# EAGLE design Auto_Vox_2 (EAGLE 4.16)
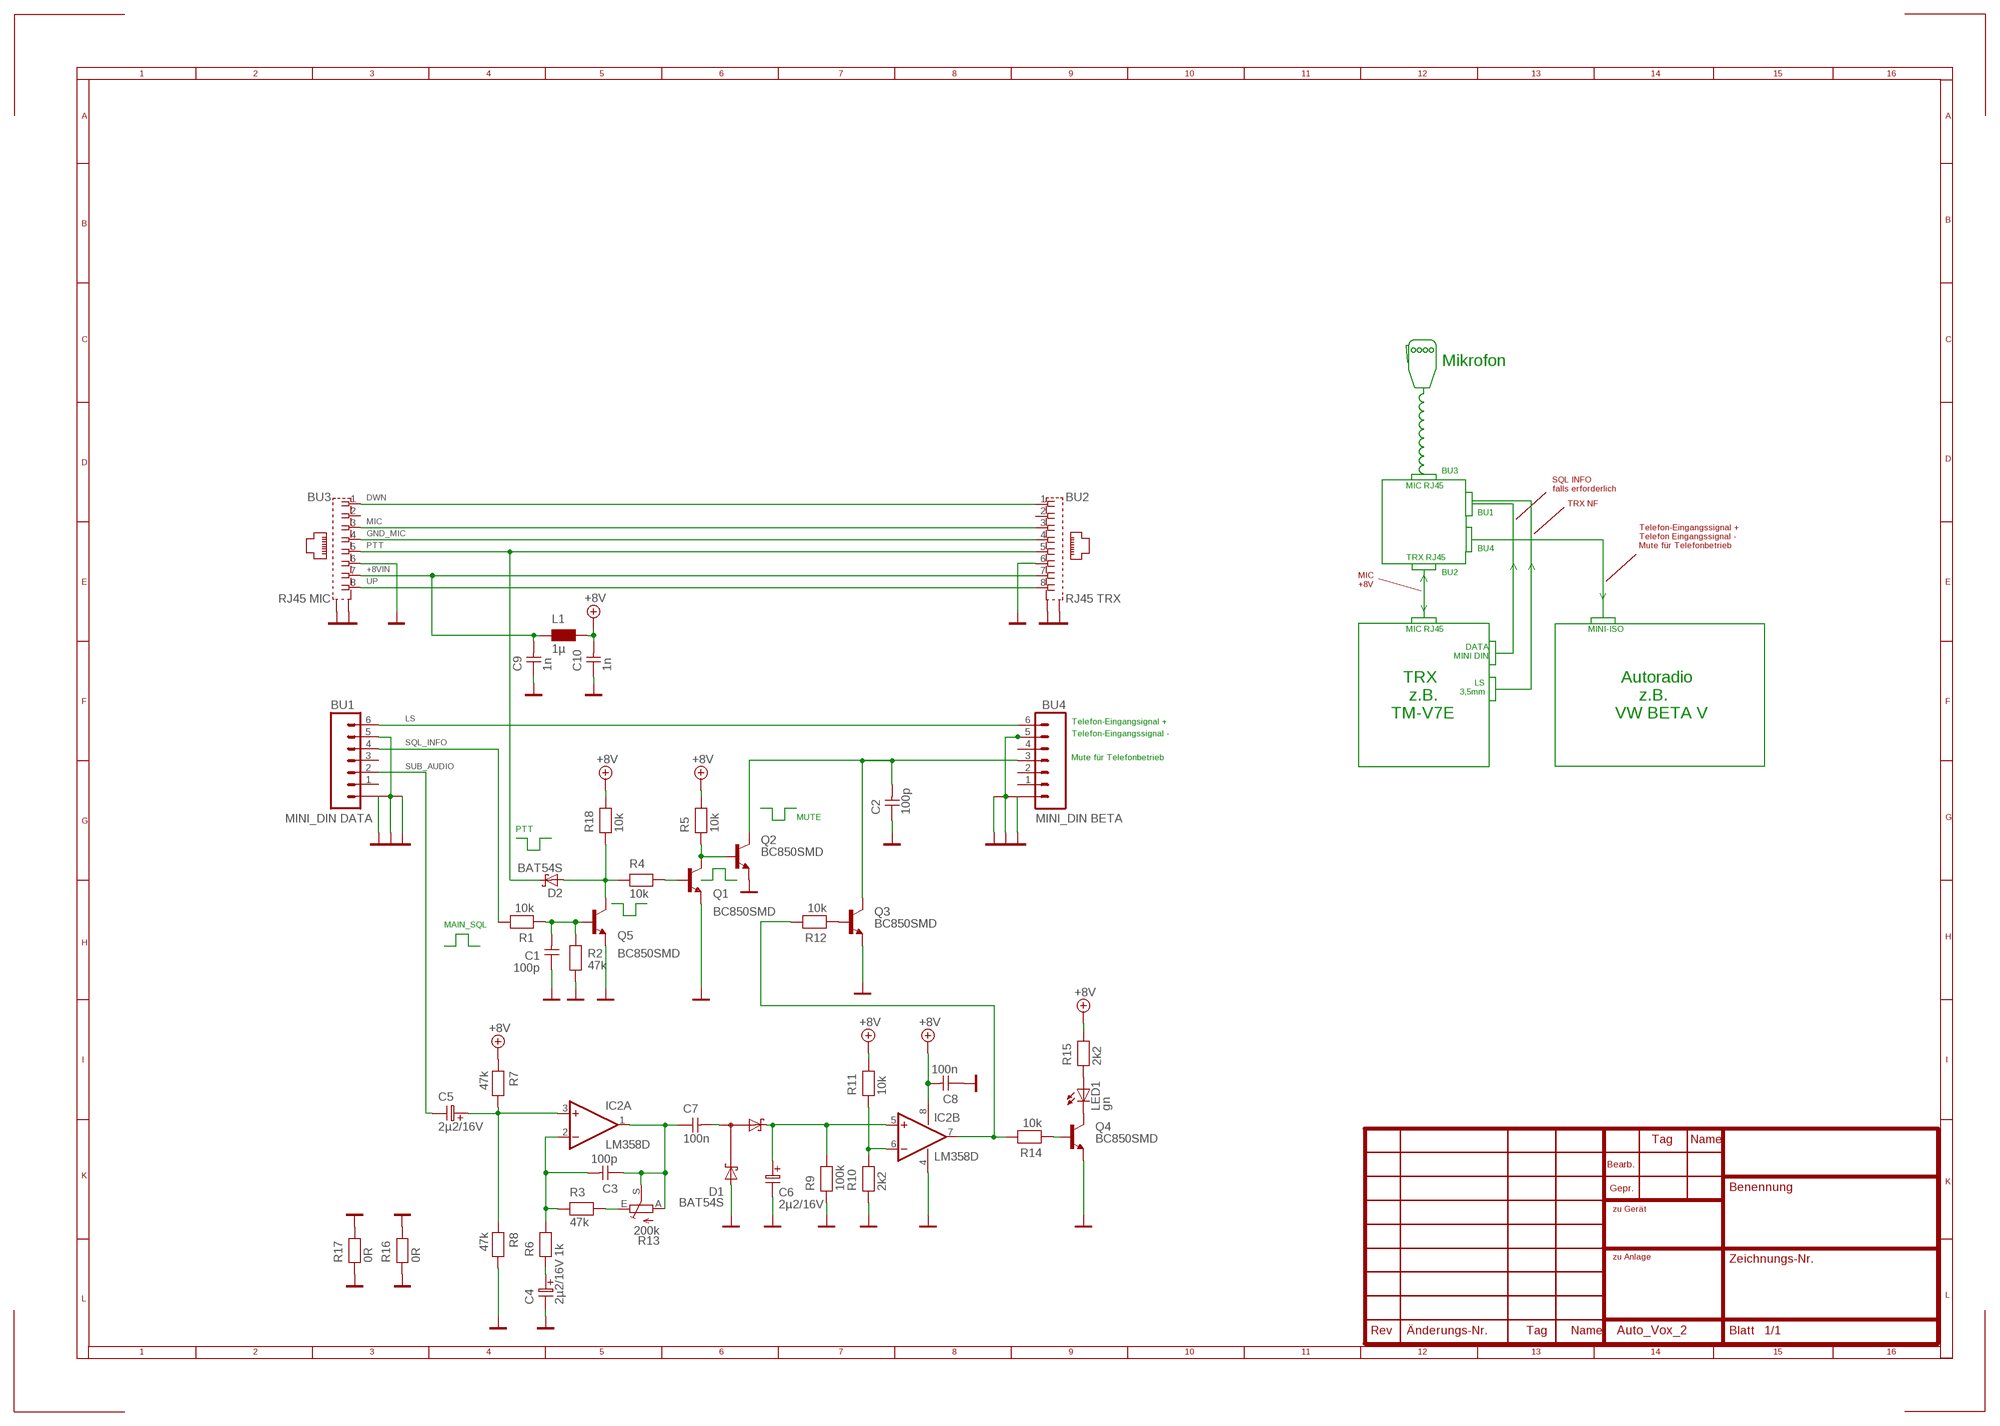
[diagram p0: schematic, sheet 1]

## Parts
BU1  MINI_DIN DATA  MINI_DIN  [MINI_DIN]
BU2  RJ45 TRX  RJ45_SHIELDED  [RJ45_SHIELDED]
BU3  RJ45 MIC  RJ45_SHIELDED  [RJ45_SHIELDED]
BU4  MINI_DIN BETA  MINI_DIN  [MINI_DIN]
C1  100p  CAPNP-0603  [0603]
C2  100p  CAPNP-0603  [0603]
C3  100p  CAPNP-0603  [0603]
C4  2µ2/16V  E-SMD_A  [E-SMD_A]
C5  2µ2/16V  E-SMD_A  [E-SMD_A]
C6  2µ2/16V  E-SMD_A  [E-SMD_A]
C7  100n  CAPNP-0603  [0603]
C8  100n  CAPNP-0603  [0603]
C9  1n  CAPNP-0603  [0603]
C10  1n  CAPNP-0603  [0603]
D1  BAT54S  [SOT23]
D2  BAT54S  BAT54  [SOT23]
IC2  LM358D  [SO08]
L1  1µ  L-0805  [0805]
LED1  gn  LED3MM  [LED3MM]
Q1  BC850SMD  [SOT23-BEC]
Q2  BC850SMD  [SOT23-BEC]
Q3  BC850SMD  [SOT23-BEC]
Q4  BC850SMD  [SOT23-BEC]
Q5  BC850SMD  [SOT23-BEC]
R1  10k  RESEU-0603  [0603]
R2  47k  RESEU-0603  [0603]
R3  47k  RESEU-0603  [0603]
R4  10k  RESEU-0603  [0603]
R5  10k  RESEU-0603  [0603]
R6  1k  RESEU-0603  [0603]
R7  47k  RESEU-0603  [0603]
R8  47k  RESEU-0603  [0603]
R9  100k  RESEU-0603  [0603]
R10  2k2  RESEU-0603  [0603]
R11  10k  RESEU-0603  [0603]
R12  10k  RESEU-0603  [0603]
R13  200k  TRIM_EU-S64Y  [S64Y]
R14  10k  RESEU-0603  [0603]
R15  2k2  RESEU-0603  [0603]
R16  0R  RESEU-0805  [0805]
R17  0R  RESEU-0805  [0805]
R18  10k  RESEU-0603  [0603]

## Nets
+8V: C8.2 C10.2 IC2.8(P:V+) L1.2 R5.2 R7.1 R11.2 R15.2 R18.2
+8VIN: BU2.7 BU3.7 C9.2 L1.1
DWN: BU2.1 BU3.1
GND: BU1.5 BU1.S1(GND1) BU1.S2(GND2) BU1.S3(GND3) BU2.6 BU2.P$1(S1) BU2.P$2(S2) BU3.6 BU3.P$1(S1) BU3.P$2(S2) BU4.5 BU4.S1(GND1) BU4.S2(GND2) BU4.S3(GND3) C1.1 C2.1 C4.N C6.N C8.1 C9.1 C10.1 D1.1(A1) IC2.4(P:V-) Q1.E Q2.E Q3.E Q4.E Q5.E R2.2 R8.2 R9.1 R10.1 R16.1 R16.2 R17.1 R17.2
GND_MIC: BU2.4 BU3.4
LS: BU1.6 BU4.6
MIC: BU2.3 BU3.3
MUTE: BU4.3 C2.2 Q2.C Q3.C
N$1: C1.2 Q5.B R1.1 R2.1
N$2: Q1.C Q2.B R5.1
N$3: C7.2 D1.3(K1A2)
N$4: C4.P R6.1
N$5: C3.2 IC2.2(A:-IN) R3.1 R6.2
N$6: C3.1 C7.1 IC2.1(A:OUT) R13.A R13.S
N$7: C5.P IC2.3(A:+IN) R7.2 R8.1
N$8: D2.1(A) Q5.C R4.1 R18.1
N$9: C6.P D1.2(K2) IC2.5(B:+IN) R9.2
N$10: IC2.6(B:-IN) R10.2 R11.1
N$11: Q3.B R12.1
N$12: IC2.7(B:OUT) R12.2 R14.2
N$13: Q1.B R4.2
N$15: R3.2 R13.E
N$16: Q4.B R14.1
N$17: LED1.K(C) Q4.C
N$18: LED1.A R15.1
PTT: BU2.5 BU3.5 D2.3(C)
SQL_INFO: BU1.4 R1.2
SUB_AUDIO: BU1.2 C5.N
UP: BU2.8 BU3.8
Unconnected: BU1.1 BU1.3 BU2.2 BU3.2 BU4.1 BU4.2 BU4.4

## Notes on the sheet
- Mikrofon
- BU3
- SQL INFO
- MIC RJ45
- falls erforderlich
- TRX NF
- BU1
- Telefon-Eingangssignal +
- Telefon Eingangssignal -
- Mute für Telefonbetrieb
- BU4
- TRX RJ45
- BU2
- MIC
- +8V
- MIC RJ45 | MINI-ISO
- DATA
- MINI DIN
- TRX | Autoradio
- LS
- 3,5mm
- z.B. | z.B.
- TM-V7E | VW BETA V
- Telefon-Eingangsignal +
- Telefon-Eingangssignal -
- Mute für Telefonbetrieb
- MUTE
- PTT
- MAIN_SQL

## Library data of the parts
BU1 BU4 = dj5qx:MINI_DIN
BU2 BU3 = dj5qx:RJ45_SHIELDED
C1-C3 C7-C10 = discrete:CAPNP-0603
C4-C6 = discrete:E-SMD_A
D1 = dj5qx:BAT54S
D2 = dj5qx:BAT54
IC2 = linear:LM358: OP AMP also LM158; LM258; LM2904 Source: http://cache.national.com/ds/LM/LM158.pdf
L1 = discrete:L-0805
LED1 = led:LED: LED
Q1-Q5 = transistor-npn:BC850*: NPN Transistor
R1-R12 R14 R15 R18 = discrete:RESEU-0603
R13 = pot:TRIM_EU-: POTENTIOMETER
R16 R17 = discrete:RESEU-0805

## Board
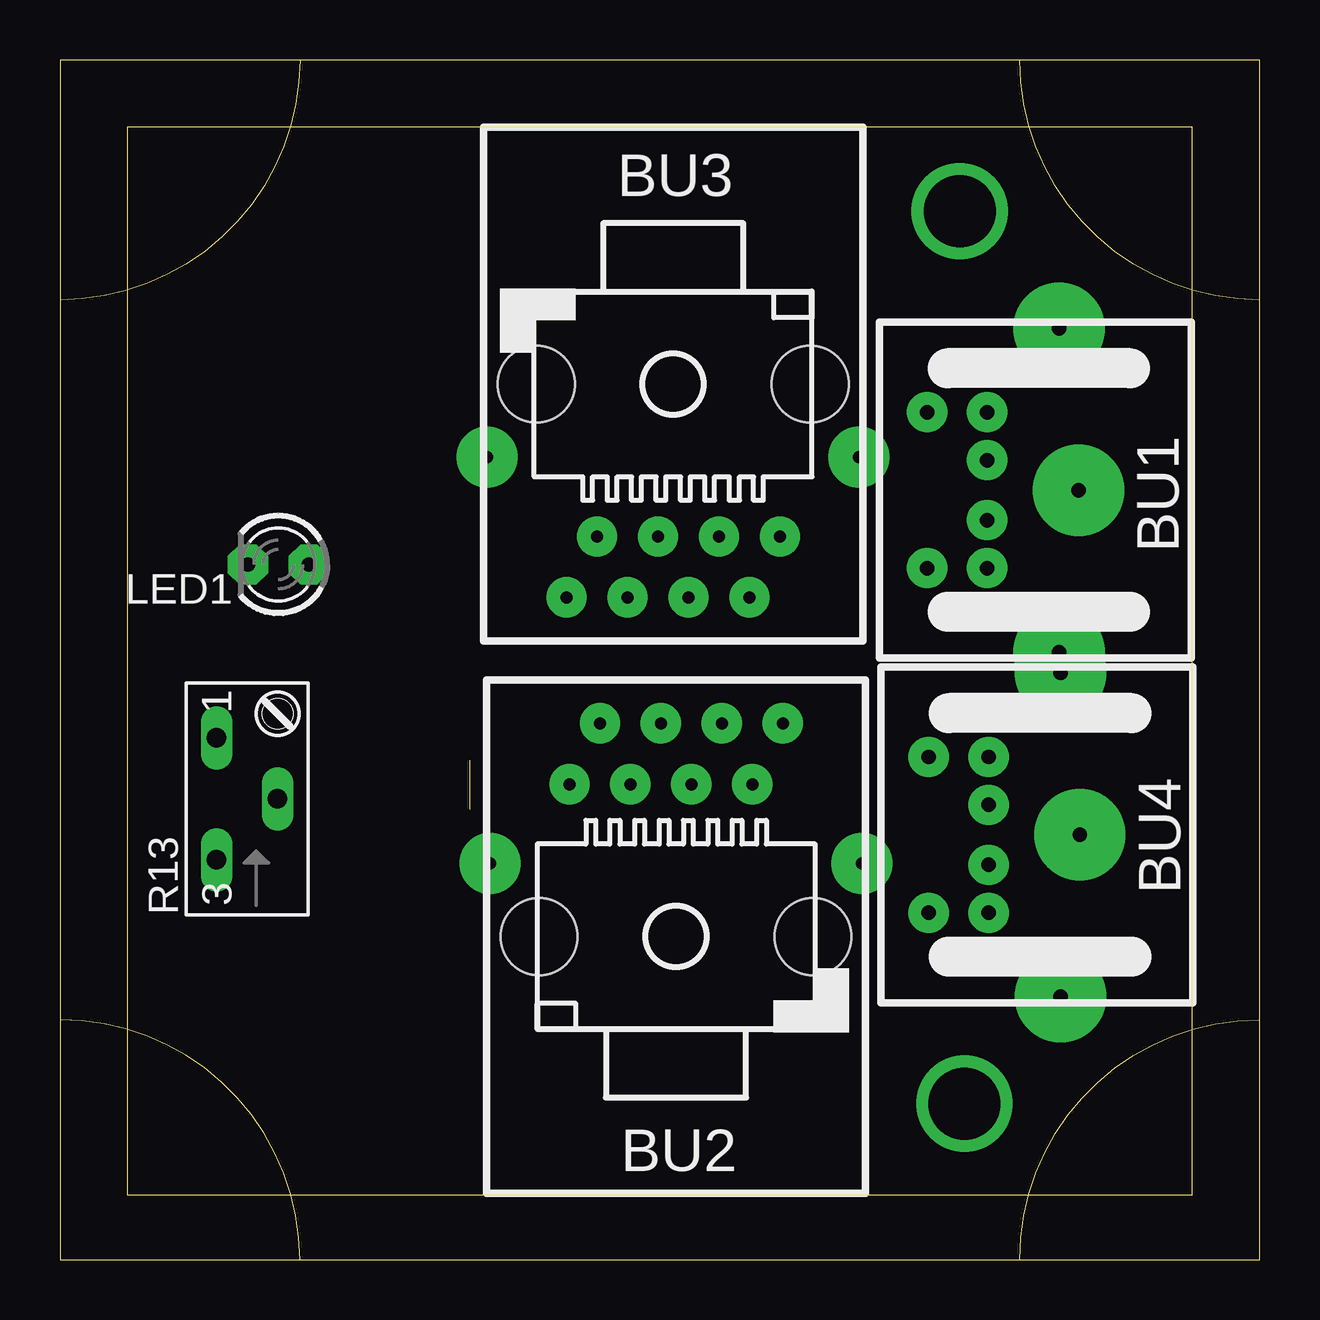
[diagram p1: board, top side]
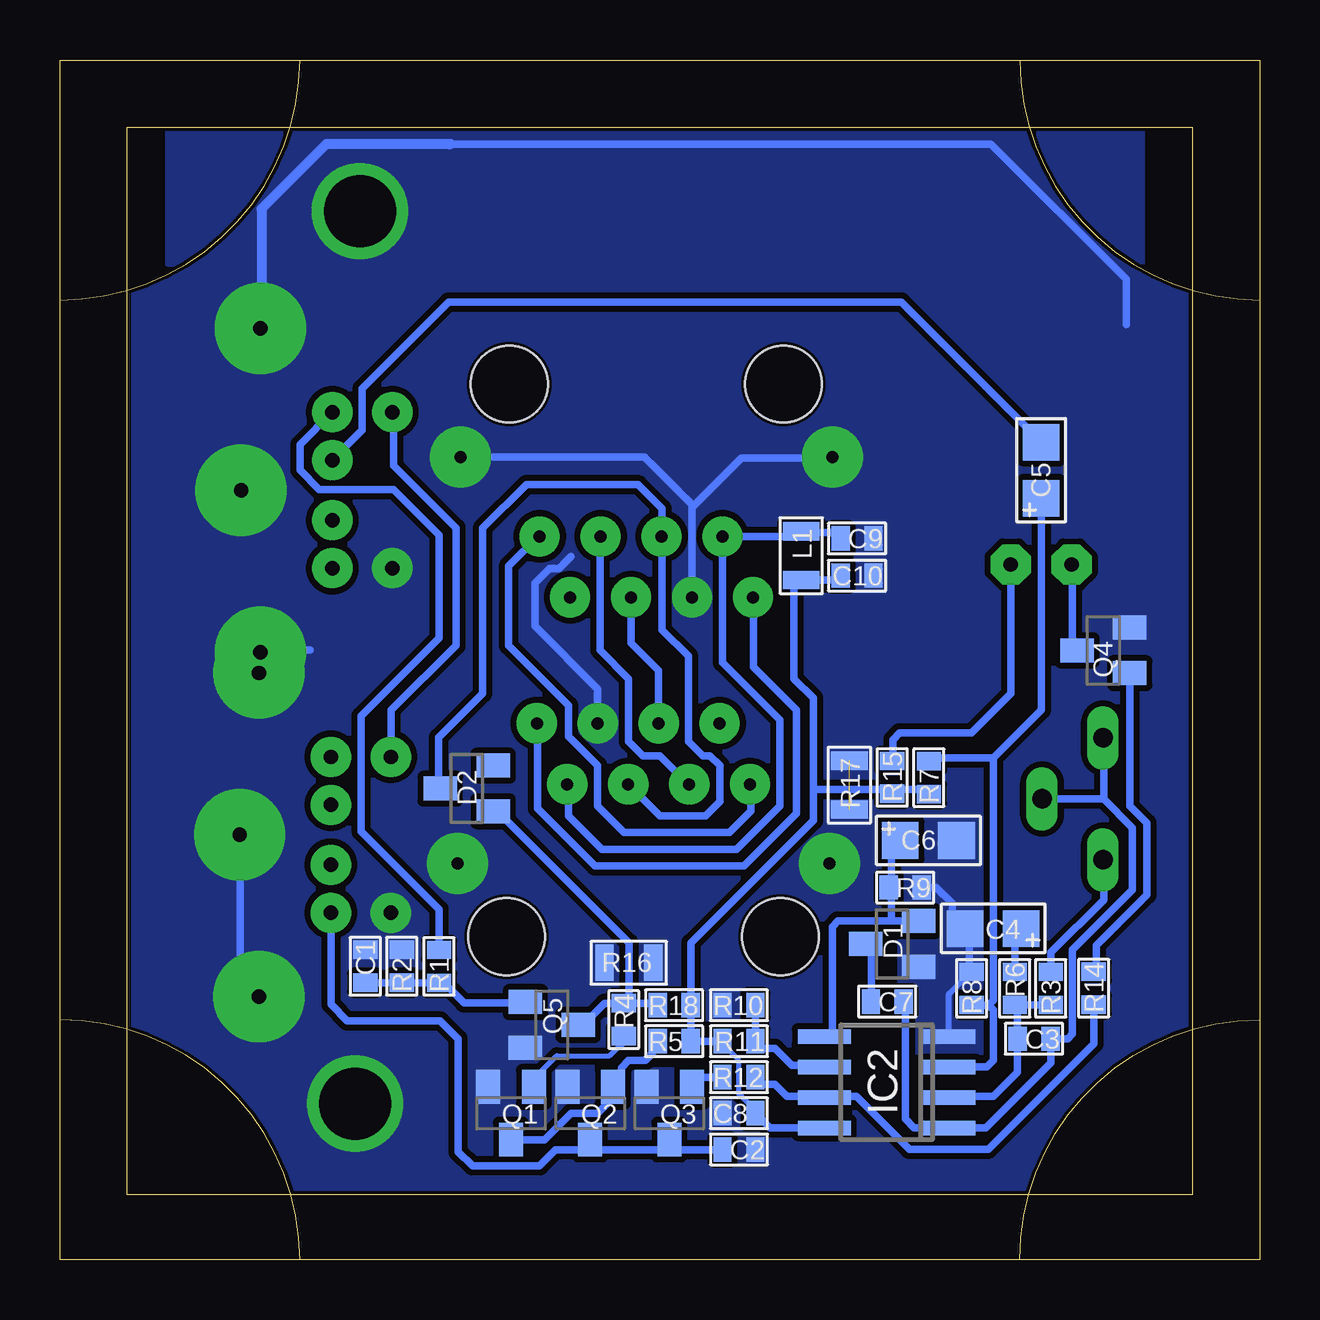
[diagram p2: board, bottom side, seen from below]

Size 50 x 50 mm. Coordinates in mm from the lower left corner, seen from the top.
Outline: 10,0 0,0 0,10
Outline: 10,0 40,0
Outline: 40,0 50,0 50,10
Outline: 50,10 50,40
Outline: 50,40 50,50 40,50
Outline: 40,50 10,50
Outline: 10,50 0,50 0,40
Outline: 0,40 0,10
Outline: 10,0 arc90 0,10
Outline: 10,50 arc-90 0,40
Outline: 40,0 arc-90 50,10
Outline: 50,40 arc-90 40,50
Outline: 2.8,2.7 47.2,2.7 47.2,47.2 2.8,47.2 2.8,2.7
Copper layers (1*16): Top 0.035mm / dielectric 1.5mm / Bottom 0.035mm
Design rules "default": minimum track width 0.2mm, minimum drill 8mil, track to track 10mil, track to pad 10mil, pad to pad 10mil, via to via 8mil, smd to smd 8mil, copper to edge 6mil, drill to drill 6mil, minimum pad ring 10mil, minimum via ring 8mil, stop-mask expansion 4mil, vias tented up to drill 0mil, thermal gap 10mil
bRestrict: area 24.2,8 to 25.3,8.3; area 15.1,11.4 to 15.4,13.8; area 21.6,9.7 to 23.1,9.9; area 24.1,11.2 to 25.9,11.4

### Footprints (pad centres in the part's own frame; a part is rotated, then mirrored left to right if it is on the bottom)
MINI_DIN = drill 0.6 pad 1.676 round: 1 1.25,-8.5; 2 -1.25,-8.5; 3 3.25,-8.5; 4 -3.25,-8.5; 5 3.25,-11; 6 -3.25,-11 | drill 0.6 pad 3.81 round: S1 -6.75,-5.5; S2 0,-4.7; S3 6.75,-5.5
RJ45_SHIELDED = drill 0.5 pad 1.676 round: 1 -4.445,6.35; 2 -3.175,8.89; 3 -1.905,6.35; 4 -0.635,8.89; 5 0.635,6.35; 6 1.905,8.89; 7 3.175,6.35; 8 4.445,8.89 | drill 0.5 pad 2.54 round: P$1 -7.75,3.05; P$2 7.75,3.05 | hole 3.2: -5.71,0; 5.71,0
0603 = smd 0.762 x 1.016: 1 -0.686,0; 2 0.686,0
E-SMD_A = smd 1.524 x 1.524: N 1.168,0; P -1.168,0
SOT23 = smd 1 x 1.4: 1 -0.95,-1.1; 2 0.95,-1.1; 3 0,1.1
SO08 = smd 0.6 x 2.2: 1 -1.905,-2.6; 2 -0.635,-2.6; 3 0.635,-2.6; 4 1.905,-2.6; 5 1.905,2.6; 6 0.635,2.6; 7 -0.635,2.6; 8 -1.905,2.6
0805 = smd 0.762 x 1.524: 1 -1.016,0; 2 1.016,0
LED3MM = drill 0.6 pad 1.676 octagon: A -1.27,0; K 1.27,0
SOT23-BEC = smd 1 x 1.4: B -0.95,-1.1; C 0,1.1; E 0.95,-1.1
S64Y = drill 0.813 long: A 2.54,1.27; E -2.54,1.27; S 0,-1.27

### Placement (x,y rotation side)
BU1  47.15,32.07 270 top
BU2  25.68,13.46 0 top
BU3  25.56,36.49 180 top
BU4  47.21,17.7 270 top
C1  37.28,12.22 270 bottom
C2  21.7,4.58 180 bottom
C3  9.4,9.2 180 bottom
C4  11.1,13.8 180 bottom
C5  9.1,32.9 90 bottom
C6  13.8,17.47 0 bottom
C7  15.52,10.75 180 bottom
C8  21.7,6.1 0 bottom
C9  16.78,30.06 180 bottom
C10  16.78,28.51 180 bottom
D1  15.32,13.16 90 bottom
D2  33.05,19.63 90 bottom
IC2  15.54,7.39 90 bottom
L1  19.1,29.34 270 bottom
LED1  9.1,28.97 180 top
Q1  31.2,6.1 180 bottom
Q2  27.9,6.1 180 bottom
Q3  24.6,6.1 180 bottom
Q4  6.51,25.39 90 bottom
Q5  29.5,9.78 270 bottom
R1  34.2,12.22 90 bottom
R2  35.75,12.22 90 bottom
R3  8.7,11.3 90 bottom
R4  26.5,10 270 bottom
R5  24.4,9.1 0 bottom
R6  10.2,11.3 270 bottom
R7  13.78,20.09 90 bottom
R8  12,11.3 90 bottom
R9  14.77,15.51 180 bottom
R10  21.7,10.6 0 bottom
R11  21.7,9.1 180 bottom
R12  21.7,7.6 0 bottom
R13  7.8,19.2 90 top
R14  6.91,11.31 270 bottom
R15  15.31,20.1 270 bottom
R16  26.29,12.37 0 bottom
R17  17.09,19.78 270 bottom
R18  24.4,10.6 0 bottom

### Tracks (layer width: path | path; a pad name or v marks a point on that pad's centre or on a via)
+8V
  Bottom 0.2: 22.4,9 21.7,8.3 21.7,6.9 21.01,6.21
  Bottom 0.254: R5.2 23.7,9 | C8.2 21.01,6.21
  Bottom 0.305: IC2.8 18.14,5.5 18,5.5 | 18,5.5 17.69,5.5 | 18,5.5 18.12,5.5 IC2.8 | 17.3,5.5 17.2,5.4 arc-90 17.3,5.5 | 17.3,5.5 18,5.5 | 13.78,19.49 13.8,19.49 R7.1 | R15.2 15.34,19.49 15.32,19.51 15.32,19.58 13.82,19.58 13.82,19.44 R7.1 | 15.38,19.49 15.41,19.46 R15.2 | 23.7,9.2 23.71,9.19 R5.2 | R7.1 13.97,19.49 | 18.6,19.58 18.6,18.3 23.7,13.2 23.7,9.2 | 18.6,19.58 18.6,23.4 19.4,24.2 19.4,28.35 19.1,28.35 L1.2 | R11.2 R5.2 | IC2.8 18.16,5.5 | 22.3,9.1 R11.2 | R5.2 | R5.2 23.7,9.2 | C10.2 17.65,28.7 17.65,28.32 L1.2 | IC2.8 18.48,5.49 18.5,5.5 18.7,5.5 | 23.7,9.2 23.7,9.11 R5.2 | R18.2 23.7,10.59 23.7,9.2 | 18.85,5.55 18.8,5.6 | 18.85,5.55 18.9,5.5 | 22.4,9 R11.2 | 21,6.09 21,6 | 21,6.09 arc-90 C8.2 | 17.3,5.5 18.7,5.5 | 18.8,5.5 arc-90 18.85,5.55 | 18.7,5.5 18.8,5.5 | C8.2 arc90 21.1,6 | C8.2 21,6.09 | 18.8,5.5 20.4,5.5 C8.2 | 15.38,19.49 15.38,19.44 R15.2 | 15.38,19.49 15.48,19.59 15.49,19.58 18.6,19.58 | L1.2 19.15,28.32
+8VIN
  Bottom 0.305: BU3.7 22.39,24.89 20,22.5 20,18.9 21.8,17.1 27.4,17.1 28.8,18.5 28.8,19.8 28.84,19.8 BU2.7 | BU3.7 22.4,30.16 22.4,30.2 | BU3.7 19.13,30.14 19.13,30.3 | 19.13,30.3 19.13,30.35 L1.1 19.13,30.33 19.13,30.3 | C9.2 17.71,30.3 19.13,30.3
DWN
  Bottom 0.305: BU2.1 21.2,19.77 21.2,18.7 22.1,17.8 26.5,17.8 27.6,18.9 27.6,20.6 28.8,21.8 28.8,23.1 31.3,25.6 31.3,28.9 30,30.2 | 30,30.2 BU3.1 30,30.2
GND  (via drill 3)  (1 unrouted)
  Bottom 0.254: R8.2 12.93,11.07 12.94,11.06 IC2.4
  Bottom 0.305: BU3.6 23.66,31.34 23.6,31.4 | 23.6,31.4 21.6,33.4 17.8,33.4 | 17.8,33.4 17.76,33.44 BU3.P$2 17.81,33.4 17.8,33.4 | BU3.P$1 25.64,33.44 23.6,31.4 | 17.93,33.47 17.9,33.5 17.9,33.4 17.8,33.4 | BU2.6 27.59,23.79 30.2,26.4 30.2,28.2 29.6,28.8 29.2,28.8 28.7,29.3 | 42.4,32 42.4,32.02 BU1.S2 | BU1.S3 41.63,25.3 41.6,25.3 41.6,25.4 | 41.6,25.4 41.6,25.37 BU1.S3 | 41.5,25.4 39.57,25.4 | 41.5,25.4 41.6,25.4 | 41.5,25.4 41.58,25.32 BU1.S3 | BU4.S1 41.71,25.19 41.5,25.4 | 36.2,14.4 36.21,14.41 BU4.5 | BU4.S2 42.5,11.74 BU4.S3 | C4.N 12.1,13.8 12.1,11.9 12,11.9 R8.2 | 13.4,9.2 13.3,9.29 | R10.1 22.39,10.8 | 12.2,13.5 12.27,13.5 C4.N | 5.56,38.96 5.56,40.86 11.2,46.5 33.8,46.5 | R9.1 14.08,15.52 13.49,15.52 12.8,14.83 12.8,13.79 12.75,13.74 12.21,13.74 | 12.21,13.74 12.19,13.74 | C4.N 12.21,13.74
  Bottom 0.406: 33.7,46.5 33.8,46.5 38.9,46.5 41.6,43.8 41.6,38.8 41.63,38.8 BU1.S1
  other vias: 37.5,43.7 37.7,6.5
  pour Bottom (no thermals): 2.5,2.5 47.5,2.5 47.5,41.7 2.5,41.7
  pour Bottom (no thermals): 45.5,47.1 4.9,47.1 4.9,41.5 45.5,41.5
GND_MIC
  Bottom 0.305: BU3.4 | BU3.4 | BU2.4 25.05,24.55 26.2,25.7 26.2,27.5 26.1,27.6 BU3.4
LS
  Bottom 0.305: BU1.6 36.13,35.3 36.1,35.3 36.1,33.1 36,33 33.5,30.5 33.5,25.6 36.2,22.9 36.2,20.9 | 36.2,20.9 36.21,20.91 BU4.6 36.2,20.9
MIC
  Bottom 0.305: BU2.3 23.79,19.81 23.8,19.8 25,21 25.7,21 26.3,21.6 26.3,24.2 27.5,25.4 27.5,30.2 27.46,30.16 BU3.3
MUTE
  Bottom 0.305: BU4.3 38.71,14.41 38.7,14.4 38.7,13.6 | 38.7,13.6 38.7,12.7 | 22.37,4.57 24.51,4.57 24.6,4.66 Q3.C 24.64,4.96 24.64,4.57 27.81,4.57 27.81,4.91 Q2.C 28.33,4.57 29.34,4.57 30.01,3.9 32.8,3.9 33.4,4.5 33.4,9.2 34.16,9.96 38.02,9.96 38.7,10.63 38.7,13.6
  Bottom 0.406: 22.35,4.57 22.37,4.57 C2.2
N$1
  Bottom 0.305: Q5.B 30.63,10.7 33.15,10.7 33.99,11.53 R1.1 R2.1 C1.2 | C1.2 | C1.2
N$2
  Bottom 0.305: 26.9,7.6 26.9,7.25 Q2.B 27,7.2 | R5.1 25.3,8.89 25.3,8.6 25.6,8.3 26.3,8.3 26.6,8 26.6,7.6 27,7.2 | 27,7.2 27,6.7 27.6,6.1 28.7,6.1 29.8,5 Q1.C
N$3
  Bottom 0.305: D1.3 16.43,13.16 16.56,13.03 16.54,13.01 16.2,13.01 16.18,12.98 16.18,10.74 C7.2
N$4
  Bottom 0.305: 9.9,13.4 10,13.5 9.93,13.57 C4.P 10.2,13.8 R6.1
N$5
  Bottom 0.305: R3.1 8.39,10.61 8.4,10.6 8.41,10.61 R6.2 10.1,10.51 C3.2 | 12.89,6.8 IC2.2 12.76,6.75 12.7,6.7 12.6,6.8 11.1,6.8 10.1,7.8 C3.2 | 10.1,9.19 C3.2
N$6
  Bottom 0.305: 6.5,21.6 6.5,21.1 | 6.5,21.6 6.5,21.8 6.53,21.77 R13.A 6.53,21.63 6.5,21.6 | 12.96,5.5 13,5.5 | 12.96,5.5 IC2.1 13.29,5.49 13.3,5.5 14.4,5.5 14.76,5.86 14.76,10.69 14.77,10.69 C7.1 | C3.1 8.5,9.4 | 12.96,5.5 11.4,5.5 8.7,8.2 C3.1 | 8.7,8.9 8.71,8.91 C3.1 | C3.1 8.7,9.19 | C3.1 8.61,9.1 | 6.5,19.2 5.3,18 5.3,15.4 7.8,12.9 7.8,9.4 8,9.2 C3.1 | 6.5,19.2 6.5,21.6 | 6.5,19.2 R13.S | C3.1
N$7
  Bottom 0.305: 11.9,10.6 11.91,10.61 R8.1 11.3,10.6 | 11.3,10.6 11.1,10.8 11.1,20.9 | IC2.3 11.38,8.03 11.1,8.3 11.1,10.4 11.3,10.6 | 9.1,31.9 C5.P | 9.1,31.9 9,32 | R7.2 13.57,20.77 | R7.2 13.88,20.79 | R7.2 13.77,20.79 | 9.1,31.9 9.1,22.9 11.1,20.9 | 13.78,20.79 13.79,20.8 | R7.2 13.78,20.79 | 13.78,20.79 13.75,20.76 | R7.2 13.74,20.81 13.74,20.9 11.1,20.9
N$8
  Bottom 0.305: Q5.C 28.02,9.78 27.94,9.86 27.94,10.03 27.3,10.67 26.42,10.67 | 26.42,10.67 26.29,10.67 26.29,13.21 31.52,18.44 32.38,18.44 32.38,18.45 D2.1 | R18.1 25.15,10.66 25.15,10.67 26.42,10.67 | 26.42,10.67 26.48,10.67 R4.1
N$9
  Bottom 0.254: 17.5,9.2 17.6,9.3 17.8,9.3
  Bottom 0.305: IC2.5 18.4,9.3 18.39,9.29 IC2.5 | IC2.5 17.8,9.3 17.8,13.87 17.57,14.11 15.34,14.11 | 15.35,15.51 15.29,15.57 15.29,15.27 15.34,15.21 15.34,17.12 14.99,17.47 C6.P | 15.35,15.51 R9.2 | 15.34,14.11 D1.2 | 15.34,14.11 15.34,14.15 15.35,14.16 15.35,15.51
N$10
  Bottom 0.305: 18,8.1 18.1,8 18.12,8.03 IC2.6 18.16,8 18.27,8.1 19.5,8.1 20.2,8.8 20.9,8.8 21.01,8.91 R11.1 21.01,9.11 R10.2
N$11
  Bottom 0.305: Q3.B 23.65,7.35 23.7,7.4 23.5,7.6 R12.1
N$12
  Bottom 0.305: IC2.7 18.1,6.7 | IC2.7 | R12.2 21,7.59 21,7.3 20.2,7.3 19.7,6.8 18.2,6.8 18.16,6.75 | IC2.7 18.16,6.75 | IC2.7 18.1,6.79 18.1,6.8 16.8,6.8 14.6,4.6 11.3,4.6 6.9,9 R14.2 7,10.61 | IC2.7 18.16,6.75
N$13
  Bottom 0.2: 26.6,9 27.1,8.5 29.3,8.5 30.2,7.6
  Bottom 0.305: 30.2,7.2 Q1.B 30.2,7.25 30.2,7.6 | R4.2 26.5,9.2 26.6,9.1 26.6,9
N$15
  Bottom 0.305: 8.69,12 R3.2 8.7,12.8 6.5,15 6.5,16.63 R13.E
N$16
  Bottom 0.305: R14.1 6.8,12 6.8,13.1 4.7,15.2 4.7,18.2 5.4,18.9 Q4.B
N$17
  Bottom 0.305: 7.8,29 LED1.K 7.8,28.94 7.8,25.4 Q4.C
N$18
  Bottom 0.305: LED1.A 10.36,23.6 12.01,21.95 15.01,21.95 15.29,21.67 15.29,20.83 15.34,20.78 | 15.34,20.78 | 15.34,20.78 R15.1
PTT
  Bottom 0.305: BU2.5 26.4,19.89 26.4,19.9 25,18.5 23.1,18.5 22.5,19.1 22.5,20.6 22.9,21 23.2,21 23.8,21.6 23.8,25.15 24.9,26.25 24.9,30.2 | 24.9,30.2 24.9,31.3 25.91,32.31 30.56,32.31 32.38,30.48 32.38,23.6 34.21,21.77 34.21,19.7 D2.3 34.21,20.07 | 24.9,30.2 24.9,30.16 BU3.5
SQL_INFO
  Bottom 0.305: BU1.4 40,33.97 40,32.9 39.2,32.1 37.3,32.1 | 37.3,32.1 37.1,32.1 | 37.3,32.1 36.1,32.1 34.2,30.2 34.2,25.9 37.45,22.65 37.45,17.85 34.2,14.6 R1.2
SUB_AUDIO
  Bottom 0.305: BU1.2 37.4,34.57 37.4,36.3 33.8,39.9 14.93,39.9 C5.N
UP
  Bottom 0.305: 30.15,22.35 30.2,22.4 | 30.15,22.35 BU2.8 30.1,22.38 | 30.15,22.35 30.1,22.3 | BU3.8 21.1,24.7 19.3,22.9 19.3,18.6 21.5,16.4 27.7,16.4 30.1,18.8 30.1,22.38 | 30.1,22.38 30.1,22.4

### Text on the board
bRestrict: DJ5QX 12/2008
